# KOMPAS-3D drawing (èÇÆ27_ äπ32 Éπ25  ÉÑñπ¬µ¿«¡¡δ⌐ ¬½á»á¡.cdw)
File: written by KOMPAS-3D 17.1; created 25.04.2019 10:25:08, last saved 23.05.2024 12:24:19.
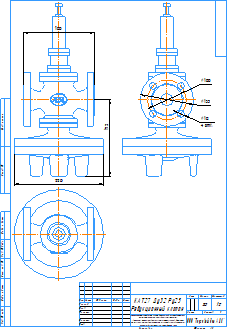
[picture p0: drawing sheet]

Sheet 1: A3, portrait

Title block, sheet 1: name: КАТ27 Ду32 Ру25 / Редукционный клапан; material: Сталь 20  ГОСТ 1050-88; mass: 26; sheets: 1; sheet format: A3; stored path: D:\Документы\Компас\Поставщики\Armstrong\Редукционный клапан GP-2000\KOMPAS 2D\GP-2000 _ Ду20 Ру25  Редукционный клапан.cdw

Views: Вид 4
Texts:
  adm
  Рама для чертежей
  Лит-Масса-Масштаб
  Материал-Предприятие
  Масштаб
  Изм.
  Лист
  № докум.
  Подп.
  Дата
  Лит.
  Разраб.
  Пров.
  Т.контр.
  Листов
  Внимание! Данный продукт является объектом авторского права ООО «Торговый Дом АДЛ».
  Запрещается изменение, копирование, распространение
  (в том числе путем копирования на другие сайты и ресурсы в Интернете)
  или любое иное использование информации и объектов без предварительного
  согласия правообладателя (ООО «Торговый Дом АДЛ»).
  Н.контр.
  Утв.
  ООО "Торговый дом АДЛ"
  Изменение
  Номер документа
  Подпись
  Обозначение документа
  Наименование изделия
  Масса изделия по ГОСТ 2.109-73
  Порядковый номер листа
  Общее количество листов в документе
  Характер работы, выполненной лицом, подписавшим документ
  Наименование или индекс предприятия, выпускающего документ
  Инв. № подл.
  Подп. и дата
  Взам. инв. №
  Инв. № дубл.
  Инвентарный номер подлинника по ГОСТ 2.501-68
  Подпись принявшего подлинник в отдел технической документации
  Инвентарный номер подлинника, взамен которого выпущен данный подлинник
  Инвентарный номер дубликата по ГОСТ 2.502-68
  Подпись принявшего дубликат в отдел технической документации
  Справ. №
  Перв. примен.
  Обозначение документа, взамен или на основании которого выпущен данный документ
  Обозначение документа, в котором впервые записан данный документ
  Подпись лица, копировавшего чертеж
  Обозначение формата листа
  !Рама для чертежа
Dimensions and other numbers on the sheet: 180; 192; 226; 100; 135; 18; 4 отв.; 1:2; 1; 26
